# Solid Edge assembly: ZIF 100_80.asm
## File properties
Title: Zylinder
Author: bmolnar
Template: iso metric assembly.asm
Last saved by: psaghy
Revision: 28
Application: Solid Edge
Username: bmolnar
Dokumentum tartalom típus: 1
Document Number: ZIF 100/80
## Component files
Mutter.par
Kit_1.par
Profilrohr.par
Kit_2.par
Kolbenstange.par
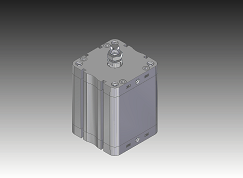
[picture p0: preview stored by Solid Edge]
